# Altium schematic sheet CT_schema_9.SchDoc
size 287 x 160 mm
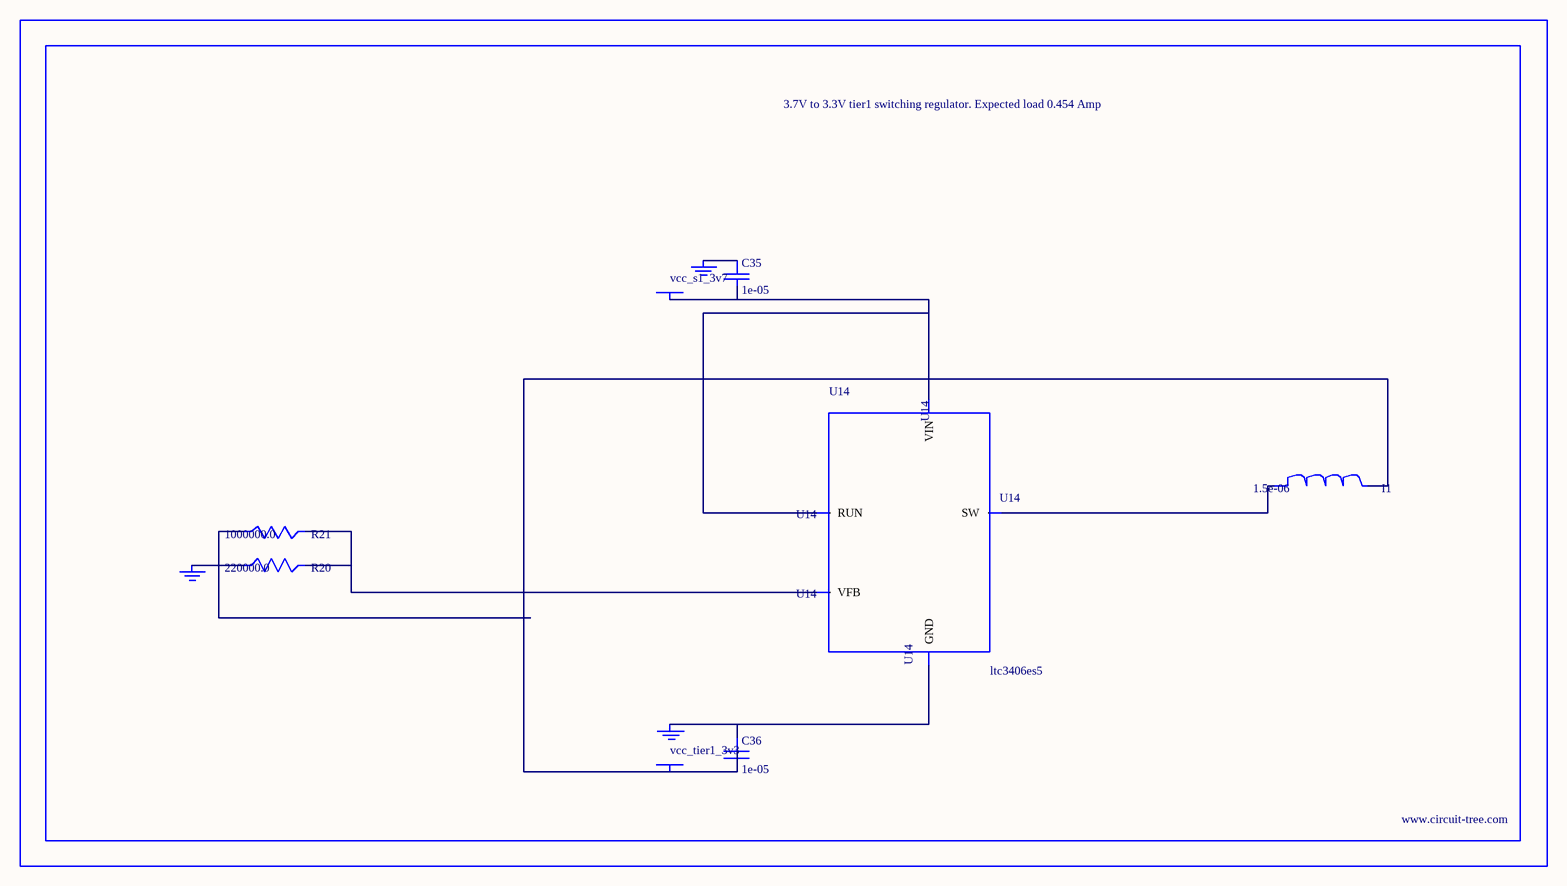
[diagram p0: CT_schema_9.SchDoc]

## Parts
BORDER8  (no value)
C35  1e-05  [C0805]
C36  1e-05  [C0805]
GND_INSTANCE_8_0  (no value)
GND_INSTANCE_8_1  (no value)
GND_INSTANCE_8_2  (no value)
I1  1.5e-06  [L0806]
POWER_INSTANCE_8_0  vcc_tier1_3v3
POWER_INSTANCE_8_1  vcc_s1_3v7
R20  220000.0  [R0603]
R21  1000000.0  [R0603]
U14  ltc3406es5  [TSOT-23-5]

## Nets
NetC35_1: C35.1 GND_INSTANCE_8_1.0(GND)
NetC35_2: C35.2 POWER_INSTANCE_8_1.0(PWR) U14.1(RUN) U14.4(VIN)
NetC36_1: C36.1 GND_INSTANCE_8_0.0(GND) U14.2(GND)
NetC36_2: C36.2 I1.2 POWER_INSTANCE_8_0.0(PWR) R21.1
NetGND_INSTANCE_8_2_0: GND_INSTANCE_8_2.0(GND) R20.1
NetI1_1: I1.1 U14.3(SW)
NetR20_2: R20.2 R21.2 U14.5(VFB)

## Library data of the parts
BORDER8 = BORDER_PAGE8
C35 C36 = C0805C106K8RACTU
GND_INSTANCE_8_0-GND_INSTANCE_8_2 = GND
I1 = L0806C1R5MDWIT
POWER_INSTANCE_8_0 POWER_INSTANCE_8_1 = PWR
R20 = RC0603JR-07220KL
R21 = RC0603JR-071ML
